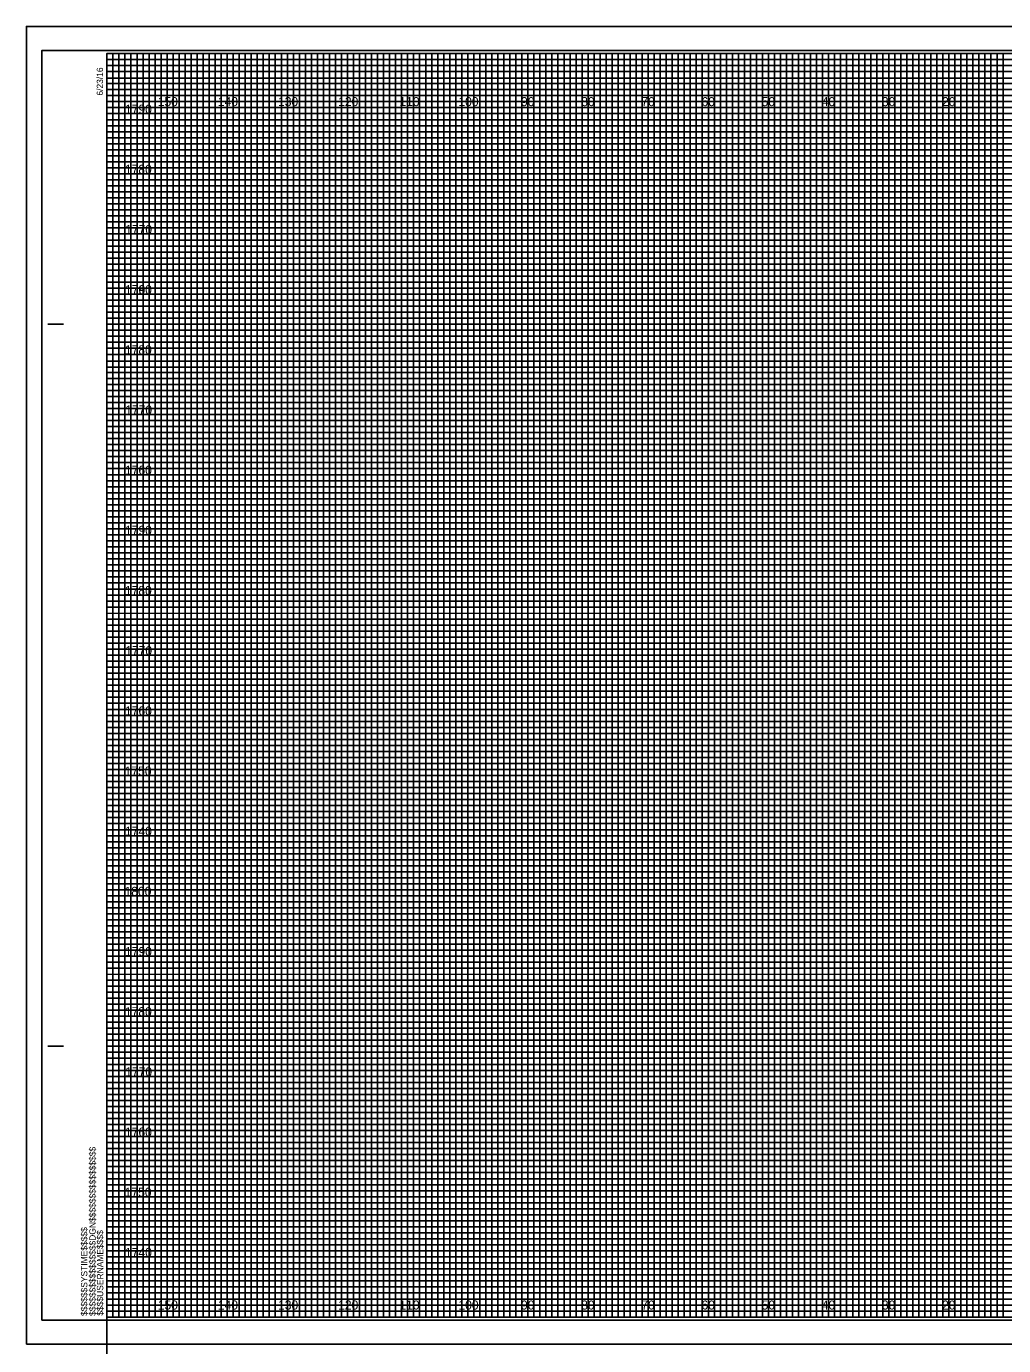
# Model space of a CAD drawing. Extents: x 791 to 1128, y -18 to 860.
# Drawn here: x 791.1 to 953.6, y 420.5 to 639.8 of the extents above; entities that cross this region are included whole.
import ezdxf

# ---------------------------------------------------------------- set-up
doc = ezdxf.new("R2010")
doc.units = 0
for name, color, linetype in [('Prop XS DDE', 7, 'Continuous'), ('Prop XS Earthwork Shape', 7, 'Continuous'), ('Prop XS Subgrade Earthwork', 7, 'Continuous'), ('Raster_Level_0', 7, 'Continuous'), ('Scratch_Level_1', 7, 'Continuous'), ('Scratch_Level_3', 7, 'Continuous'), ('Sheet Cross Section CELL', 7, 'Continuous'), ('Sheet Cross Section Grid Minor 2 CELL', 7, 'Continuous'), ('Sheet Cutting Line CELL', 7, 'Continuous'), ('Sheet DOT Grid CELL', 7, 'Continuous'), ('Sheet Plot Border Inside CELL', 7, 'Continuous'), ('Sheet Plot Border Outside CELL', 7, 'Continuous')]:
    doc.layers.add(name, color=color, linetype=linetype)

msp = doc.modelspace()

# ---------------------------------------------------------------- linework, layer by layer
at = {"layer": 'Prop XS DDE'}
for p, q in [((804.53, 634.25), (1064.53, 634.25)), ((1064.53, 633.23), (804.53, 633.23)), ((804.53, 633.23), (804.53, 632.25)), ((804.53, 632.25), (1064.53, 632.25)), ((1064.53, 631.14), (804.53, 631.14)), ((804.53, 631.14), (804.53, 629.25)), ((804.53, 629.25), (1124.53, 629.25))]:
    msp.add_line(p, q, dxfattribs=at)
for points in [[(804.53, 628.25), (1074.53, 628.25), (1124.53, 628.25), (1124.53, 627.25), (804.53, 627.25)], [(804.53, 626.25), (1124.53, 626.25), (1124.53, 624.25), (804.53, 624.25)], [(804.53, 623.25), (1124.53, 623.25), (1124.53, 622.25), (804.53, 622.23)], [(804.53, 621.25), (1124.53, 621.25), (1124.53, 619.25), (804.53, 619.25)], [(804.53, 618.25), (1124.53, 618.25), (1124.53, 617.25), (804.53, 617.25)], [(804.53, 616.25), (1124.53, 616.25), (1124.53, 614.25), (804.53, 614.25)], [(804.53, 613.25), (1124.53, 613.25), (1124.53, 612.25), (804.53, 612.25)], [(804.53, 611.25), (1124.53, 611.25), (1124.53, 609.25), (804.53, 609.25)], [(804.53, 608.25), (1124.53, 608.25), (1124.53, 607.25), (804.53, 607.25)], [(804.53, 606.25), (1124.53, 606.25), (1124.53, 604.25), (804.53, 604.25)], [(804.53, 603.25), (1124.53, 603.25), (1124.53, 602.25), (804.53, 602.25)], [(804.53, 601.25), (1124.53, 601.25), (1124.53, 599.2), (1124.53, 598.25), (1124.53, 597.25), (804.53, 597.25)], [(804.53, 599.25), (1124.53, 599.25), (1124.53, 598.25), (804.53, 598.25)], [(804.53, 596.25), (1124.53, 596.25), (1124.53, 594.25), (804.53, 594.28)], [(804.53, 594.28), (1124.53, 594.25), (1124.53, 593.25), (804.53, 593.25)], [(804.53, 592.25), (1124.53, 592.25), (1124.53, 591.25), (804.53, 591.25)], [(804.53, 589.25), (1124.53, 589.25), (1124.53, 588.25), (804.53, 588.25)], [(804.53, 587.25), (1124.53, 587.25), (1124.53, 586.25), (804.53, 586.25)], [(804.46, 584.14), (1124.53, 584.14), (1124.53, 583.13), (804.46, 583.13)], [(804.53, 582.25), (1124.53, 582.25), (1124.53, 581.25), (804.53, 581.25)], [(804.53, 579.25), (1124.53, 579.25), (1124.53, 578.25), (804.53, 578.25)], [(804.53, 577.25), (1124.53, 577.25), (1124.53, 576.25), (804.53, 576.25)], [(804.53, 574.25), (1124.53, 574.25), (1124.53, 573.25), (804.53, 573.25)], [(804.53, 572.25), (1124.53, 572.25), (1124.53, 571.25), (804.53, 571.25)], [(804.53, 569.25), (1124.53, 569.25), (1124.53, 568.25), (804.53, 568.25)], [(804.53, 567.25), (1124.53, 567.25), (1124.53, 566.25), (804.53, 566.25)], [(804.53, 564.25), (1124.53, 564.25), (1124.52, 563.23), (804.53, 563.25)], [(804.53, 562.25), (1124.53, 562.25), (1124.53, 561.25), (804.53, 561.25)], [(804.53, 559.25), (1124.53, 559.25), (1124.53, 558.25), (804.53, 558.25)], [(804.53, 557.25), (1124.53, 557.25), (1124.53, 556.25), (804.53, 556.25)], [(804.53, 554.25), (1124.53, 554.25), (1124.53, 553.25), (804.53, 553.25)], [(804.53, 552.25), (1124.53, 552.25), (1124.53, 551.25), (804.53, 551.25)], [(804.53, 549.25), (1124.53, 549.25), (1124.53, 548.25), (804.53, 548.25)], [(804.53, 547.25), (1124.53, 547.25), (1124.53, 546.25), (804.53, 546.25)], [(804.53, 544.25), (1124.53, 544.25), (1124.53, 543.25), (804.53, 543.25)], [(804.53, 542.24), (1124.6, 542.16), (1124.53, 541.25), (804.53, 541.25)], [(804.53, 539.25), (1124.53, 539.25), (1124.53, 538.25), (804.53, 538.25)], [(804.53, 537.25), (1124.53, 537.25), (1124.53, 536.25), (804.53, 536.25)], [(804.53, 534.25), (1124.53, 534.25), (1124.53, 533.25), (804.53, 533.25)], [(804.53, 532.25), (1124.53, 532.25), (1124.53, 531.25), (804.53, 531.25)], [(804.53, 529.25), (1124.53, 529.25), (1124.53, 528.25), (804.53, 528.25)], [(804.53, 527.25), (1124.53, 527.25), (1124.53, 526.25), (804.53, 526.25)], [(804.53, 524.25), (1124.53, 524.25), (1124.53, 523.25), (804.53, 523.25)], [(804.53, 522.25), (1124.53, 522.25), (1124.53, 521.25), (804.53, 521.25)], [(804.53, 519.25), (1124.53, 519.25), (1124.53, 518.25), (804.53, 518.25)], [(804.53, 517.25), (1124.53, 517.25), (1124.53, 516.25), (804.53, 516.25)], [(804.53, 514.25), (1124.53, 514.25), (1124.53, 513.25), (804.53, 513.25)], [(804.53, 512.25), (1124.53, 512.25), (1124.53, 511.25), (804.53, 511.25)], [(804.53, 509.25), (1124.53, 509.25), (1124.53, 508.25), (804.53, 508.25)], [(804.53, 507.25), (1124.53, 507.25), (1124.53, 506.25), (804.53, 506.25)], [(804.53, 504.25), (1124.53, 504.25), (1124.52, 503.23), (804.53, 503.25)], [(804.53, 502.25), (1124.53, 502.25), (1124.53, 501.25), (804.53, 501.25)], [(804.53, 499.25), (1124.53, 499.25), (1124.53, 498.25), (804.53, 498.25)], [(804.53, 497.25), (1124.53, 497.25), (1124.53, 496.25), (804.53, 496.25)], [(804.53, 494.25), (1124.53, 494.25), (1124.53, 493.25), (804.53, 493.25)], [(804.53, 492.25), (1124.53, 492.25), (1124.53, 491.25), (804.53, 491.25)], [(804.53, 489.25), (1124.53, 489.25), (1124.53, 488.25), (804.53, 488.25)], [(804.53, 487.25), (1124.53, 487.25), (1124.53, 486.25), (804.53, 486.25)], [(804.53, 484.25), (1124.53, 484.25), (1124.53, 483.25), (804.53, 483.25)], [(804.53, 482.24), (1124.6, 482.16), (1124.53, 481.25), (804.53, 481.25)], [(804.53, 479.25), (1124.53, 479.25), (1124.53, 478.25), (804.53, 478.25)], [(804.53, 477.25), (1124.53, 477.25), (1124.53, 476.25), (804.53, 476.25)], [(804.53, 474.25), (1124.53, 474.25), (1124.53, 473.25), (804.53, 473.25)], [(804.53, 472.25), (1124.53, 472.25), (1124.53, 471.25), (804.53, 471.25)], [(804.53, 469.25), (1124.53, 469.25), (1124.53, 468.25), (804.53, 468.25)], [(804.53, 467.25), (1124.53, 467.25), (1124.53, 466.25), (804.53, 466.25)], [(804.53, 464.25), (1124.53, 464.25), (1124.53, 463.25), (804.53, 463.25)], [(804.53, 462.25), (1124.53, 462.25), (1124.53, 461.25), (804.53, 461.25)], [(804.53, 459.25), (1124.53, 459.25), (1124.53, 458.25), (804.53, 458.25)], [(804.53, 457.25), (1124.53, 457.25), (1124.53, 456.25), (804.53, 456.25)], [(804.53, 454.25), (1124.53, 454.25), (1124.53, 453.25), (804.53, 453.25)], [(804.53, 452.25), (1124.53, 452.25), (1124.53, 451.25), (804.53, 451.25)], [(804.53, 449.25), (1124.53, 449.25), (1124.53, 448.25), (804.53, 448.25)], [(804.53, 447.25), (1124.53, 447.25), (1124.53, 446.25), (804.53, 446.25)], [(804.53, 444.25), (1124.53, 444.25), (1124.53, 443.25), (804.53, 443.25)], [(804.53, 442.25), (1124.53, 442.25), (1124.53, 441.25), (804.53, 441.25)], [(804.53, 439.25), (1124.53, 439.25), (1124.53, 438.25), (804.53, 438.25)], [(804.53, 437.25), (1124.53, 437.25), (1124.53, 436.25), (804.53, 436.25)], [(804.53, 434.25), (1124.53, 434.25), (1124.53, 433.25), (804.53, 433.25)], [(804.53, 432.25), (1124.53, 432.25), (1124.53, 431.25), (804.53, 431.25)], [(804.53, 429.25), (1124.53, 429.25), (1124.53, 428.25), (804.53, 428.25)], [(804.53, 427.25), (1124.53, 427.25), (1124.53, 426.25), (804.53, 426.25)]]:
    msp.add_lwpolyline(points, dxfattribs=at)
at = {"layer": 'Prop XS Earthwork Shape'}
for points in [[(804.53, 635.25), (809.53, 635.25), (809.53, 425.25), (819.53, 425.25), (819.53, 635.25), (829.53, 635.25), (829.53, 425.25), (839.53, 425.25), (839.53, 635.25), (849.53, 635.25), (849.53, 425.25), (859.53, 425.25), (859.53, 635.25), (869.53, 635.25), (869.53, 425.25), (879.53, 425.25), (879.53, 635.25), (889.53, 635.25), (889.53, 425.25), (899.53, 425.25), (899.53, 635.25), (909.53, 635.25), (909.53, 425.25), (919.53, 425.25), (919.53, 635.25), (929.53, 635.25), (929.53, 425.25), (939.53, 425.25), (939.53, 635.25), (949.53, 635.25), (949.53, 425.25), (959.53, 425.25)], [(804.53, 630.25), (1079.53, 630.25)], [(804.53, 610.25), (1124.53, 610.25), (1124.53, 620.25), (804.53, 620.25)], [(804.53, 590.25), (1124.53, 590.25), (1124.53, 600.25), (804.53, 600.25)], [(804.53, 570.25), (1124.53, 570.25), (1124.53, 580.25), (804.53, 580.25)], [(804.53, 550.25), (1124.53, 550.25), (1124.53, 560.25), (804.53, 560.25)], [(804.53, 530.25), (1124.53, 530.25), (1124.53, 540.25), (804.53, 540.25)], [(804.53, 510.25), (1124.53, 510.25), (1124.53, 520.25), (804.53, 520.25)], [(804.53, 490.25), (1124.53, 490.25), (1124.53, 500.25), (804.53, 500.25)], [(804.53, 470.25), (1124.53, 470.25), (1124.53, 480.25), (804.53, 480.25)], [(804.53, 450.25), (1124.53, 450.25), (1124.53, 460.25), (804.53, 460.25)], [(804.53, 430.25), (1124.53, 430.25), (1124.53, 440.25), (804.53, 440.25)]]:
    msp.add_lwpolyline(points, dxfattribs=at)
at = {"layer": 'Prop XS Subgrade Earthwork'}
msp.add_line((804.53, 425.25), (804.53, 312.36), dxfattribs=at)
at = {"layer": 'Scratch_Level_1'}
for p, q in [((814.53, 635.25), (804.53, 635.25)), ((814.53, 425.25), (814.53, 635.25)), ((834.53, 635.25), (824.53, 635.25)), ((824.53, 635.25), (824.53, 425.25)), ((834.53, 425.25), (834.53, 635.25)), ((854.53, 635.25), (844.53, 635.25)), ((844.53, 635.25), (844.53, 425.25)), ((854.53, 425.25), (854.53, 635.25)), ((874.53, 635.25), (864.53, 635.25)), ((864.53, 635.25), (864.53, 425.25)), ((874.53, 425.25), (874.53, 635.25)), ((894.53, 635.25), (884.53, 635.25)), ((884.53, 635.25), (884.53, 425.25)), ((894.53, 425.25), (894.53, 635.25)), ((914.53, 635.25), (904.53, 635.25)), ((904.53, 635.25), (904.53, 425.25)), ((914.53, 425.25), (914.53, 635.25)), ((934.53, 635.25), (924.53, 635.25)), ((924.53, 635.25), (924.53, 425.25)), ((934.53, 425.25), (934.53, 635.25)), ((954.53, 635.25), (944.53, 635.25)), ((944.53, 635.25), (944.53, 425.25)), ((824.53, 425.25), (814.53, 425.25)), ((844.53, 425.25), (834.53, 425.25)), ((864.53, 425.25), (854.53, 425.25)), ((884.53, 425.25), (874.53, 425.25)), ((904.53, 425.25), (894.53, 425.25)), ((924.53, 425.25), (914.53, 425.25)), ((944.53, 425.25), (934.53, 425.25))]:
    msp.add_line(p, q, dxfattribs=at)
for points in [[(804.53, 625.25), (1124.53, 625.25), (1124.53, 615.25), (804.53, 615.25)], [(804.53, 605.25), (1124.53, 605.25), (1124.53, 595.25), (804.53, 595.25)], [(804.53, 585.25), (1124.53, 585.25), (1124.53, 575.25), (804.53, 575.25)], [(804.53, 565.25), (1124.53, 565.25), (1124.53, 555.25), (804.53, 555.25)], [(804.53, 545.25), (1124.53, 545.25), (1124.53, 535.25), (804.53, 535.25)], [(804.53, 525.25), (1124.53, 525.25), (1124.53, 515.25), (804.53, 515.25)], [(804.53, 505.25), (1124.53, 505.25), (1124.53, 495.25), (804.53, 495.25)], [(804.53, 485.25), (1124.53, 485.25), (1124.53, 475.25), (804.53, 475.25)], [(804.53, 465.25), (1124.53, 465.25), (1124.53, 455.25), (804.53, 455.25)], [(804.53, 445.25), (1124.53, 445.25), (1124.53, 435.25), (804.53, 435.25)]]:
    msp.add_lwpolyline(points, dxfattribs=at)
at = {"layer": 'Sheet Cross Section CELL'}
for p, q in [((794.73, 590.25), (797.23, 590.25)), ((794.83, 590.25), (797.33, 590.25)), ((794.73, 470.25), (797.23, 470.25)), ((794.83, 470.25), (797.33, 470.25)), ((804.53, 425.25), (804.53, 425.25)), ((804.53, 425.25), (804.53, 425.25)), ((804.53, 425.25), (804.53, 425.25)), ((804.53, 425.25), (804.53, 425.25)), ((804.53, 425.25), (804.53, 425.25)), ((804.53, 425.25), (804.53, 425.25)), ((804.53, 425.25), (804.53, 425.25))]:
    msp.add_line(p, q, dxfattribs=at)
msp.add_lwpolyline([(1124.53, 635.25), (804.53, 635.25), (804.53, 425.25), (1124.53, 425.25)], close=True, dxfattribs=at)
at = {"layer": 'Sheet Cross Section Grid Minor 2 CELL'}
for points in [[(804.53, 425.25), (805.53, 425.25), (805.53, 635.25), (806.53, 635.25), (806.53, 425.25)], [(806.53, 425.25), (807.53, 425.25), (807.53, 635.25), (808.53, 635.25), (808.53, 425.25)], [(809.53, 425.25), (810.53, 425.25), (810.53, 635.25), (811.53, 635.25), (811.53, 425.25)], [(811.53, 425.25), (812.53, 425.25), (812.53, 635.25), (813.53, 635.25), (813.53, 425.25)], [(814.53, 425.25), (815.53, 425.25), (815.53, 635.25), (816.53, 635.25), (816.53, 425.25)], [(816.53, 425.25), (817.53, 425.25), (817.53, 635.25), (818.53, 635.25), (818.53, 425.25)], [(819.53, 425.25), (820.53, 425.25), (820.53, 635.25), (821.53, 635.25), (821.53, 425.25)], [(821.53, 425.25), (822.53, 425.25), (822.53, 635.25), (823.53, 635.25), (823.53, 425.25)], [(824.53, 425.25), (825.53, 425.25), (825.53, 635.25), (826.53, 635.25), (826.53, 425.25)], [(826.53, 425.25), (827.53, 425.25), (827.53, 635.25), (828.53, 635.25), (828.53, 425.25)], [(829.53, 425.25), (830.53, 425.25), (830.53, 635.25), (831.53, 635.25), (831.53, 425.25)], [(831.53, 425.25), (832.53, 425.25), (832.53, 635.25), (833.53, 635.25), (833.53, 425.25)], [(834.53, 425.25), (835.53, 425.25), (835.53, 635.25), (836.53, 635.25), (836.53, 425.25)], [(836.53, 425.25), (837.53, 425.25), (837.53, 635.25), (838.53, 635.25), (838.53, 425.25)], [(839.53, 425.25), (840.53, 425.25), (840.53, 635.25), (841.53, 635.25), (841.53, 425.25)], [(841.53, 425.25), (842.53, 425.25), (842.53, 635.25), (843.53, 635.25), (843.53, 425.25)], [(844.53, 425.25), (845.53, 425.25), (845.53, 635.25), (846.53, 635.25), (846.53, 425.25)], [(846.53, 425.25), (847.53, 425.25), (847.53, 635.25), (848.53, 635.25), (848.53, 425.25)], [(849.53, 425.25), (850.53, 425.25), (850.53, 635.25), (851.53, 635.25), (851.53, 425.25)], [(851.53, 425.25), (852.53, 425.25), (852.53, 635.25), (853.53, 635.25), (853.53, 425.25)], [(854.53, 425.25), (855.53, 425.25), (855.53, 635.25), (856.53, 635.25), (856.53, 425.25)], [(856.53, 425.25), (857.53, 425.25), (857.53, 635.25), (858.53, 635.25), (858.53, 425.25)], [(859.53, 425.25), (860.53, 425.25), (860.53, 635.25), (861.53, 635.25), (861.53, 425.25)], [(861.53, 425.25), (862.53, 425.25), (862.53, 635.25), (863.53, 635.25), (863.53, 425.25)], [(864.53, 425.25), (865.53, 425.25), (865.53, 635.25), (866.53, 635.25), (866.53, 425.25)], [(866.53, 425.25), (867.53, 425.25), (867.53, 635.25), (868.53, 635.25), (868.53, 425.25)], [(869.53, 425.25), (870.53, 425.25), (870.53, 635.25), (871.53, 635.25), (871.53, 425.25)], [(871.53, 425.25), (872.53, 425.25), (872.53, 635.25), (873.53, 635.25), (873.53, 425.25)], [(874.53, 425.25), (875.53, 425.25), (875.53, 635.25), (876.53, 635.25), (876.53, 425.25)], [(876.53, 425.25), (877.53, 425.25), (877.53, 635.25), (878.53, 635.25), (878.53, 425.25)], [(879.53, 425.25), (880.53, 425.25), (880.53, 635.25), (881.53, 635.25), (881.53, 425.25)], [(881.53, 425.25), (882.53, 425.25), (882.53, 635.25), (883.53, 635.25), (883.53, 425.25)], [(884.53, 425.25), (885.53, 425.25), (885.53, 635.25), (886.53, 635.25), (886.53, 425.25)], [(886.53, 425.25), (887.53, 425.25), (887.53, 635.25), (888.53, 635.25), (888.53, 425.25)], [(889.53, 425.25), (890.53, 425.25), (890.53, 635.25), (891.53, 635.25), (891.53, 425.25)], [(891.53, 425.25), (892.53, 425.25), (892.53, 635.25), (893.53, 635.25), (893.53, 425.25)], [(894.53, 425.25), (895.53, 425.25), (895.53, 635.25), (896.53, 635.25), (896.53, 425.25)], [(896.53, 425.25), (897.53, 425.25), (897.53, 635.25), (898.53, 635.25), (898.53, 425.25)], [(899.53, 425.25), (900.53, 425.25), (900.53, 635.25), (901.53, 635.25), (901.53, 425.25)], [(901.53, 425.25), (902.53, 425.25), (902.53, 635.25), (903.53, 635.25), (903.53, 425.25)], [(904.53, 425.25), (905.53, 425.25), (905.53, 635.25), (906.53, 635.25), (906.53, 425.25)], [(906.53, 425.25), (907.53, 425.25), (907.53, 635.25), (908.53, 635.25), (908.53, 425.25)], [(909.53, 425.25), (910.53, 425.25), (910.53, 635.25), (911.53, 635.25), (911.53, 425.25)], [(911.53, 425.25), (912.53, 425.25), (912.53, 635.25), (913.53, 635.25), (913.53, 425.25)], [(914.53, 425.25), (915.53, 425.25), (915.53, 635.25), (916.53, 635.25), (916.53, 425.25)], [(916.53, 425.25), (917.53, 425.25), (917.53, 635.25), (918.53, 635.25), (918.53, 425.25)], [(919.53, 425.25), (920.53, 425.25), (920.53, 635.25), (921.53, 635.25), (921.53, 425.25)], [(921.53, 425.25), (922.53, 425.25), (922.53, 635.25), (923.53, 635.25), (923.53, 425.25)], [(924.53, 425.25), (925.53, 425.25), (925.53, 635.25), (926.53, 635.25), (926.53, 425.25)], [(926.53, 425.25), (927.53, 425.25), (927.53, 635.25), (928.53, 635.25), (928.53, 425.25)], [(929.53, 425.25), (930.53, 425.25), (930.53, 635.25), (931.53, 635.25), (931.53, 425.25)], [(931.53, 425.25), (932.53, 425.25), (932.53, 635.25), (933.53, 635.25), (933.53, 425.25)], [(934.53, 425.25), (935.53, 425.25), (935.53, 635.25), (936.53, 635.25), (936.53, 425.25)], [(936.53, 425.25), (937.53, 425.25), (937.53, 635.25), (938.53, 635.25), (938.53, 425.25)], [(939.53, 425.25), (940.53, 425.25), (940.53, 635.25), (941.53, 635.25), (941.53, 425.25)], [(941.53, 425.25), (942.53, 425.25), (942.53, 635.25), (943.53, 635.25), (943.53, 425.25)], [(944.53, 425.25), (945.53, 425.25), (945.53, 635.25), (946.53, 635.25), (946.53, 425.25)], [(946.53, 425.25), (947.53, 425.25), (947.53, 635.25), (948.53, 635.25), (948.53, 425.25)], [(949.53, 425.25), (950.53, 425.25), (950.53, 635.25), (951.53, 635.25), (951.53, 425.25)], [(951.53, 425.25), (952.53, 425.25), (952.53, 635.25), (953.53, 635.25), (953.53, 425.25)]]:
    msp.add_lwpolyline(points, dxfattribs=at)
at = {"layer": 'Sheet Cutting Line CELL'}
for p, q in [((1127.83, 639.75), (791.13, 639.75)), ((791.13, 639.75), (791.13, 420.75)), ((791.13, 420.75), (1127.83, 420.75))]:
    msp.add_line(p, q, dxfattribs=at)
at = {"layer": 'Sheet DOT Grid CELL'}
for p, q in [((814.53, 425.25), (814.53, 635.25)), ((824.53, 425.25), (824.53, 635.25)), ((834.53, 425.25), (834.53, 635.25)), ((844.53, 425.25), (844.53, 635.25)), ((854.53, 425.25), (854.53, 635.25)), ((864.53, 425.25), (864.53, 635.25)), ((874.53, 425.25), (874.53, 635.25)), ((884.53, 425.25), (884.53, 635.25)), ((894.53, 425.25), (894.53, 635.25)), ((904.53, 425.25), (904.53, 635.25)), ((914.53, 425.25), (914.53, 635.25)), ((924.53, 425.25), (924.53, 635.25)), ((934.53, 425.25), (934.53, 635.25)), ((944.53, 425.25), (944.53, 635.25)), ((804.53, 625.25), (1124.53, 625.25)), ((804.53, 615.25), (1124.53, 615.25)), ((804.53, 605.25), (1124.53, 605.25)), ((804.53, 595.25), (1124.53, 595.25)), ((804.53, 585.25), (1124.53, 585.25)), ((804.53, 575.25), (1124.53, 575.25)), ((804.53, 565.25), (1124.53, 565.25)), ((804.53, 555.25), (1124.53, 555.25)), ((804.53, 545.25), (1124.53, 545.25)), ((804.53, 535.25), (1124.53, 535.25)), ((804.53, 525.25), (1124.53, 525.25)), ((804.53, 515.25), (1124.53, 515.25)), ((804.53, 505.25), (1124.53, 505.25)), ((804.53, 495.25), (1124.53, 495.25)), ((804.53, 485.25), (1124.53, 485.25)), ((804.53, 475.25), (1124.53, 475.25)), ((804.53, 465.25), (1124.53, 465.25)), ((804.53, 455.25), (1124.53, 455.25)), ((804.53, 445.25), (1124.53, 445.25)), ((804.53, 435.25), (1124.53, 435.25))]:
    msp.add_line(p, q, dxfattribs=at)
at = {"layer": 'Sheet Plot Border Inside CELL'}
msp.add_lwpolyline([(793.73, 424.75), (1126.93, 424.75), (1126.93, 635.75), (793.73, 635.75)], close=True, dxfattribs=at)
at = {"layer": 'Sheet Plot Border Outside CELL'}
msp.add_lwpolyline([(791.13, 420.75), (1127.83, 420.75), (1127.83, 639.75), (791.13, 639.75)], close=True, dxfattribs=at)

# ---------------------------------------------------------------- texts
at = {"layer": 'Raster_Level_0'}
for s, p in [('150', (812.98, 626.5)), ('140', (822.98, 626.5)), ('130', (832.98, 626.5)), ('120', (842.98, 626.5)), ('110', (853.16, 626.5)), ('100', (862.98, 626.5)), ('90', (873.39, 626.5)), ('80', (883.39, 626.5)), ('70', (893.39, 626.5)), ('60', (903.39, 626.5)), ('50', (913.39, 626.5)), ('40', (923.39, 626.5)), ('30', (933.39, 626.5)), ('20', (943.39, 626.5)), ('150', (812.98, 426.5)), ('140', (822.98, 426.5)), ('130', (832.98, 426.5)), ('120', (842.98, 426.5)), ('110', (853.16, 426.5)), ('100', (862.98, 426.5)), ('90', (873.39, 426.5)), ('80', (883.39, 426.5)), ('70', (893.39, 426.5)), ('60', (903.39, 426.5)), ('50', (913.39, 426.5)), ('40', (923.39, 426.5)), ('30', (933.39, 426.5)), ('20', (943.39, 426.5))]:
    msp.add_text(s, height=1.5, dxfattribs=at).set_placement(p)
at = {"layer": 'Scratch_Level_3'}
for s, p in [('1790', (807.54, 625.25)), ('1780', (807.52, 615.25)), ('1770', (807.57, 605.25)), ('1790', (807.54, 595.25)), ('1760', (807.54, 595.25)), ('1780', (807.52, 585.25)), ('1770', (807.57, 575.25)), ('1760', (807.54, 565.25)), ('1790', (807.54, 555.25)), ('1780', (807.52, 545.25)), ('1770', (807.57, 535.25)), ('1760', (807.54, 525.25)), ('1750', (807.49, 515.25)), ('1740', (807.54, 505.25)), ('1800', (807.46, 495.25)), ('1790', (807.54, 485.25)), ('1780', (807.52, 475.25)), ('1770', (807.57, 465.25)), ('1760', (807.54, 455.25)), ('1750', (807.49, 445.25)), ('1740', (807.54, 435.25))]:
    msp.add_text(s, height=1.5, dxfattribs=at).set_placement(p)
at = {"layer": 'Sheet Cross Section CELL'}
for s, p in [('6/23/16', (803.88, 628.25)), ('$$$$$$$$$$$$$$$$DGN$$$$$$$$$$$$$$$$', (802.65, 425.43)), ('$$$$$$SYSTIME$$$$$', (801.27, 425.43)), ('$$$$USERNAME$$$$', (803.91, 425.48))]:
    msp.add_text(s, height=1.05, rotation=90, dxfattribs=at).set_placement(p)

doc.saveas('drawing.dxf')
